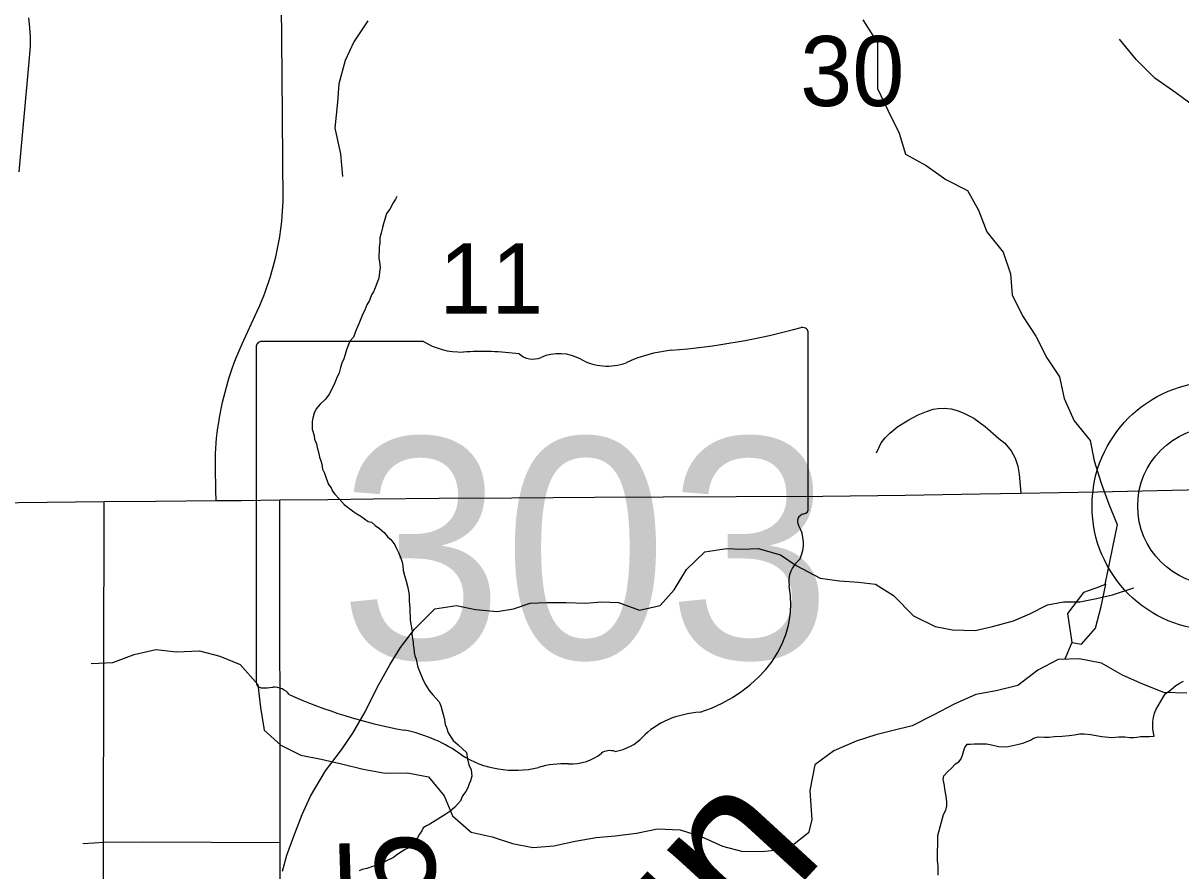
# Model space of a CAD drawing. Extents: x -21.1 to 50.3, y 0 to 22.1.
# Drawn here: x 2.692 to 3.383, y 20.064 to 20.57 of the extents above; entities that cross this region are included whole.
import ezdxf

# ---------------------------------------------------------------- set-up
doc = ezdxf.new("R2010")
doc.units = 0
for name, color, linetype in [('GM_X_Minor_Lake', 7, 'Continuous'), ('GM_X_Minor_River', 7, 'Continuous'), ('GM_X_Minor_River_Text', 7, 'Continuous'), ('GM_X_Section_Text', 7, 'Continuous'), ('GM_X_State_Location', 7, 'Continuous'), ('GM_X_State_Route', 7, 'Continuous'), ('GM_X_State_Shield', 7, 'Continuous'), ('GM_X_Township_Road', 7, 'Continuous'), ('GM_X_Township_Road_Text', 7, 'Continuous'), ('GM_X_Unincorporated', 7, 'Continuous')]:
    doc.layers.add(name, color=color, linetype=linetype)

msp = doc.modelspace()

# ---------------------------------------------------------------- linework, layer by layer
at = {"layer": 'GM_X_Minor_Lake'}
for points in [[(3.3386, 20.2351), (3.33479, 20.23356), (3.32528, 20.23012), (3.31579, 20.21756), (3.3184, 20.20027)], [(3.3386, 20.2351), (3.33479, 20.23356), (3.32528, 20.23012), (3.31579, 20.21756), (3.3184, 20.20027)], [(3.31837, 20.20027), (3.32419, 20.19932), (3.33254, 20.20883), (3.33595, 20.22177), (3.33859, 20.23508)], [(3.3184, 20.20027), (3.32419, 20.19932), (3.33254, 20.20883), (3.33595, 20.22177), (3.3386, 20.2351)]]:
    msp.add_lwpolyline(points, dxfattribs=at)
at = {"layer": 'GM_X_Minor_River'}
for points in [[(2.8981, 20.57159), (2.88975, 20.55907), (2.88444, 20.54808), (2.88064, 20.53404), (2.87988, 20.52304), (2.87835, 20.50749), (2.88175, 20.49232), (2.88288, 20.47867)], [(3.19351, 20.57225), (3.20228, 20.55857), (3.20232, 20.53118), (3.20843, 20.51826), (3.2153, 20.50458), (3.21912, 20.49203), (3.23131, 20.4852), (3.24311, 20.47685), (3.25606, 20.4704), (3.26255, 20.45862), (3.26751, 20.44569), (3.27742, 20.43353), (3.28163, 20.42061), (3.28279, 20.40806), (3.28889, 20.39552), (3.2969, 20.38335), (3.30339, 20.37043), (3.31102, 20.35903), (3.3137, 20.3461), (3.31981, 20.3328), (3.32934, 20.32102), (3.33164, 20.30886), (3.33584, 20.29555), (3.34043, 20.283), (3.34539, 20.27084), (3.33812, 20.23491)], [(3.39183, 20.52039), (3.3804, 20.52874), (3.36783, 20.53747), (3.35678, 20.54849), (3.34687, 20.56065)], [(2.91541, 20.46672), (2.91463, 20.46521), (2.91308, 20.46295), (2.91112, 20.45918), (2.90919, 20.45654), (2.90839, 20.45389), (2.90759, 20.45124), (2.90679, 20.4482), (2.90598, 20.44479), (2.90519, 20.44214), (2.90514, 20.4391), (2.90473, 20.43644), (2.9047, 20.43416), (2.90466, 20.43188), (2.90463, 20.4296), (2.90499, 20.42769), (2.90532, 20.42426), (2.90491, 20.42161), (2.90487, 20.41932), (2.90447, 20.41743), (2.90328, 20.4144), (2.90249, 20.41213), (2.90132, 20.40986), (2.90015, 20.40798), (2.89896, 20.40457), (2.89741, 20.40193), (2.89622, 20.3989), (2.89505, 20.39664), (2.89387, 20.39361), (2.89269, 20.39058), (2.89112, 20.38718), (2.88954, 20.38264), (2.88722, 20.38039), (2.88525, 20.37509), (2.88445, 20.37244), (2.88365, 20.36979), (2.88248, 20.36714), (2.88168, 20.36449), (2.88088, 20.36146), (2.87931, 20.35806), (2.87813, 20.35503), (2.87656, 20.35163), (2.87499, 20.34861), (2.87267, 20.3456), (2.86959, 20.3426), (2.86727, 20.33997), (2.86609, 20.33732), (2.86529, 20.33429), (2.86488, 20.33239), (2.86485, 20.32973), (2.86482, 20.32783), (2.86591, 20.32401), (2.86626, 20.32172), (2.86736, 20.31904), (2.86771, 20.31676), (2.86845, 20.31485), (2.8688, 20.31294), (2.86916, 20.31103), (2.86988, 20.30874), (2.87062, 20.30683), (2.87096, 20.30378), (2.87207, 20.30148), (2.87316, 20.29843), (2.87463, 20.2946), (2.87613, 20.29268), (2.87686, 20.29077), (2.87836, 20.28884), (2.88099, 20.28615), (2.88398, 20.28268), (2.88963, 20.27842), (2.89151, 20.27725), (2.89377, 20.2757), (2.89603, 20.27415), (2.8983, 20.2726), (2.90019, 20.27219), (2.90245, 20.27026), (2.90508, 20.26832), (2.90771, 20.266), (2.90996, 20.26331), (2.91184, 20.26176), (2.91408, 20.25869), (2.91519, 20.25639), (2.9163, 20.25409), (2.91777, 20.25065), (2.9185, 20.24835), (2.91885, 20.24607), (2.9192, 20.2434), (2.91991, 20.24035), (2.92101, 20.23691), (2.92173, 20.23386), (2.92208, 20.23195), (2.92244, 20.23004), (2.92279, 20.22814), (2.92275, 20.22509), (2.92307, 20.2209), (2.92303, 20.21824), (2.92338, 20.21596), (2.92335, 20.21368), (2.9237, 20.21139), (2.92405, 20.2091), (2.92441, 20.20719)], [(2.84704, 20.06375), (2.84969, 20.07323), (2.85387, 20.08461), (2.8588, 20.09751), (2.86374, 20.10851), (2.87284, 20.12368), (2.88233, 20.1362), (2.88915, 20.14606), (2.89636, 20.15895), (2.90357, 20.17337), (2.91116, 20.18702), (2.91761, 20.19726), (2.92595, 20.20826), (2.93809, 20.2204), (2.95098, 20.2223), (2.96235, 20.22002), (2.97524, 20.21889), (2.9851, 20.2204), (2.99495, 20.22382), (3.00481, 20.2242), (3.01618, 20.2242), (3.02793, 20.22383), (3.03779, 20.22458), (3.04764, 20.22421), (3.06015, 20.21966), (3.07266, 20.22231), (3.081, 20.2318), (3.08821, 20.24394), (3.09921, 20.25455), (3.1121, 20.25645), (3.12158, 20.25607), (3.13105, 20.25645), (3.14432, 20.25266), (3.15379, 20.24622), (3.16819, 20.23863), (3.17956, 20.23712), (3.19094, 20.23636), (3.20117, 20.23522), (3.21178, 20.2284), (3.2239, 20.21626), (3.23679, 20.20982), (3.24702, 20.20792), (3.26067, 20.20755), (3.2709, 20.20983), (3.28342, 20.21324), (3.29327, 20.21741), (3.30389, 20.22272), (3.31337, 20.22462), (3.32322, 20.22462), (3.33308, 20.22652), (3.34256, 20.22879), (3.35545, 20.23297)], [(2.92441, 20.20719), (2.92437, 20.20491), (2.92472, 20.20263), (2.92508, 20.20072), (2.92505, 20.19882), (2.92541, 20.19691), (2.92575, 20.19424), (2.9261, 20.19234), (2.92684, 20.19043), (2.92756, 20.18737), (2.92791, 20.18547), (2.92975, 20.18126), (2.93122, 20.17743), (2.93271, 20.17475), (2.93457, 20.17168), (2.93681, 20.16899), (2.93869, 20.16706), (2.94056, 20.16475), (2.94167, 20.16245), (2.94239, 20.1594), (2.94311, 20.15673), (2.94384, 20.15406), (2.94418, 20.15139), (2.94491, 20.14948), (2.94601, 20.14642), (2.94899, 20.14181), (2.952, 20.13911), (2.95463, 20.13679), (2.95688, 20.13448), (2.95759, 20.13067), (2.9583, 20.12723), (2.95978, 20.12417), (2.96011, 20.12036), (2.95931, 20.11771), (2.95852, 20.11582), (2.95773, 20.11355), (2.95656, 20.11128), (2.95462, 20.10865), (2.95344, 20.10562), (2.95151, 20.10374), (2.94997, 20.10186), (2.94689, 20.09924), (2.94458, 20.09775), (2.93499, 20.0918), (2.93308, 20.09069), (2.93116, 20.08957), (2.93037, 20.08768), (2.92883, 20.0858), (2.92765, 20.08353), (2.92533, 20.08052), (2.92301, 20.07789), (2.92071, 20.07678), (2.9188, 20.07567), (2.91534, 20.07343), (2.91342, 20.07194), (2.90883, 20.06972), (2.90499, 20.06749), (2.90079, 20.06641), (2.89735, 20.06531), (2.89468, 20.06459), (2.89277, 20.06385)], [(3.31842, 20.20028), (3.31424, 20.19035)], [(2.73293, 20.18779), (2.74578, 20.1884), (2.75856, 20.19317), (2.77137, 20.19606), (2.78388, 20.19476), (2.79749, 20.19537), (2.80964, 20.19217), (2.82184, 20.18707), (2.83226, 20.17511), (2.83402, 20.16148), (2.83615, 20.14785), (2.84614, 20.13892), (2.85797, 20.13306), (2.87012, 20.13061), (2.88227, 20.12779), (2.89519, 20.1246), (2.90847, 20.12218), (2.92171, 20.12241), (2.93423, 20.11997), (2.94351, 20.10875), (2.94864, 20.09669), (2.95978, 20.08702), (2.97231, 20.08421), (2.98448, 20.08024), (2.99663, 20.0778), (3.0091, 20.07878), (3.02191, 20.08166), (3.03435, 20.08377), (3.04569, 20.08473), (3.05852, 20.08647), (3.07096, 20.08897), (3.08459, 20.08845), (3.09714, 20.08449), (3.10972, 20.07864), (3.12189, 20.07544), (3.13512, 20.07567), (3.14871, 20.07704), (3.16103, 20.08675)], [(3.38701, 20.17011), (3.37331, 20.17047), (3.36075, 20.1754), (3.34857, 20.18071), (3.336, 20.18792), (3.32268, 20.19057), (3.31012, 20.19017), (3.29796, 20.18369), (3.28617, 20.17455), (3.27324, 20.17149), (3.26107, 20.16919), (3.24814, 20.16347), (3.23597, 20.15699), (3.22305, 20.15051), (3.21087, 20.14745), (3.20136, 20.14516), (3.18957, 20.14134), (3.17626, 20.13562), (3.16486, 20.12724), (3.16194, 20.11191), (3.16318, 20.09436), (3.16114, 20.08656)], [(3.3672, 20.15545), (3.36761, 20.15811), (3.3684, 20.16), (3.37268, 20.16717), (3.37424, 20.16981), (3.37655, 20.1713), (3.38039, 20.17467), (3.38308, 20.17615), (3.38499, 20.17727)], [(3.23849, 20.06137), (3.23852, 20.06404), (3.23856, 20.0667), (3.23823, 20.07013), (3.23843, 20.08496), (3.24164, 20.09747), (3.2432, 20.10011), (3.24362, 20.10276), (3.24365, 20.10504), (3.24332, 20.10847), (3.24261, 20.11267), (3.24227, 20.11495), (3.24155, 20.11839), (3.24196, 20.12066), (3.24428, 20.12329), (3.24659, 20.12516), (3.24891, 20.12779), (3.25082, 20.12891), (3.25237, 20.13079), (3.25316, 20.13306), (3.25396, 20.13571), (3.25437, 20.13761), (3.25591, 20.13949), (3.25782, 20.13946), (3.2601, 20.13981), (3.26276, 20.13977), (3.26505, 20.13974), (3.26733, 20.13971), (3.2696, 20.1393), (3.27453, 20.13809), (3.27948, 20.13802), (3.28482, 20.13909), (3.28901, 20.14017), (3.2936, 20.14201), (3.29552, 20.14313), (3.29819, 20.14385), (3.302, 20.1438), (3.30466, 20.14376), (3.30809, 20.14409), (3.31266, 20.14441), (3.31684, 20.14474), (3.31989, 20.14507), (3.32294, 20.14579), (3.32561, 20.14576), (3.32941, 20.14532), (3.33623, 20.14409), (3.34231, 20.14362), (3.3465, 20.14394), (3.34992, 20.1439), (3.35296, 20.14348), (3.35524, 20.14344), (3.35715, 20.1438), (3.35944, 20.14415), (3.36248, 20.14411), (3.36476, 20.14408), (3.36743, 20.14442), (3.36673, 20.14861), (3.36675, 20.15051), (3.36679, 20.15318), (3.3672, 20.15545)]]:
    msp.add_lwpolyline(points, dxfattribs=at)
at = {"layer": 'GM_X_State_Route'}
for points in [[(2.84553, 20.28548), (2.87423, 20.28579), (2.9014, 20.28614), (2.94057, 20.28643), (2.98403, 20.28675)], [(2.98403, 20.28675), (3.03343, 20.28706), (3.0743, 20.28731), (3.11789, 20.28743), (3.16976, 20.2878), (3.21883, 20.28836), (3.26368, 20.28902), (3.28793, 20.28953), (3.33361, 20.29027), (3.39622, 20.29163), (3.41981, 20.29237)], [(2.40939, 20.28139), (2.43498, 20.28152), (2.47747, 20.28205), (2.48841, 20.28218), (2.54659, 20.28269), (2.61253, 20.28328), (2.65498, 20.28367), (2.66882, 20.28379), (2.68951, 20.28398), (2.74059, 20.28444), (2.77141, 20.28472), (2.80741, 20.28506), (2.8227, 20.2852), (2.84553, 20.28548)]]:
    msp.add_lwpolyline(points, dxfattribs=at)
at = {"layer": 'GM_X_State_Shield'}
for p, q in [((3.161, 20.28045), (3.161, 20.38513)), ((2.83141, 20.37673), (2.83141, 20.17661)), ((2.93118, 20.38017), (2.83466, 20.38017)), ((3.16096, 20.28047), (3.161, 20.28045))]:
    msp.add_line(p, q, dxfattribs=at)
for centre, major_axis, start_param, end_param in [((3.04359, 20.653), (0.34952, 0), 4.814394, 5.042369), ((3.15734, 20.38557), (0.00367, 0), 6.141152, 7.989035), ((2.83519, 20.37716), (0.00382, 0), 1.712693, 3.28349), ((2.95416, 20.4034), (0.03703, 0), 4.042523, 4.731795), ((2.96644, 20.26782), (0.13295, 0), 1.404758, 1.657858), ((2.99663, 20.37819), (0.01068, 0), 3.836095, 5.185415), ((3.01231, 20.35506), (0.02221, 0), 0.950623, 2.079405), ((3.04098, 20.38679), (0.02672, 0), 4.081561, 5.145723), ((3.08818, 20.31905), (0.07032, 0), 1.699011, 2.107814), ((3.15708, 20.28004), (0.00393, 0), 5.05454, 6.418171), ((3.16015, 20.27276), (0.00568, 0), 1.883978, 3.671073), ((3.12402, 20.25953), (0.03409, 0), 5.934695, 6.695948), ((3.17414, 20.23664), (0.0248, 0), 2.387724, 3.262537), ((3.06317, 20.22332), (0.08742, 0), 5.101752, 6.440018), ((2.83522, 20.17617), (0.00385, 0), 3.00124, 4.508301), ((2.83581, 20.19664), (0.0294, 0), 4.665946, 4.897461), ((2.84182, 20.16506), (0.0106, 0), 0.519207, 1.627899), ((2.97565, 20.34486), (0.2524, 0), 4.195997, 4.488961), ((3.10003, 20.12043), (0.04788, 0), 1.647645, 2.488434), ((2.9004, 20.0867), (0.07897, 0), 0.823519, 1.323587), ((3.03937, 20.15721), (0.02824, 0), 4.937069, 5.64225), ((3.04258, 20.1297), (0.00752, 0), 1.147584, 2.315152), ((2.98581, 20.16407), (0.05011, 0), 4.026481, 4.996735), ((3.01476, 20.09488), (0.04118, 0), 1.495662, 1.94098), ((3.01842, 20.14908), (0.0267, 0), 4.691044, 5.507374)]:
    msp.add_ellipse(centre, major_axis=major_axis, ratio=0.8, start_param=start_param, end_param=end_param, dxfattribs=at)
at = {"layer": 'GM_X_Township_Road'}
for points in [[(2.80741, 20.28506), (2.8073, 20.29088), (2.80704, 20.30543), (2.80711, 20.31316), (2.80726, 20.31626), (2.80746, 20.31937), (2.80774, 20.32246), (2.80809, 20.32554), (2.80851, 20.32862), (2.80898, 20.33168), (2.80949, 20.33474), (2.81005, 20.33778), (2.81066, 20.34081), (2.81131, 20.34383), (2.81202, 20.34684), (2.81277, 20.34982), (2.81356, 20.35279), (2.81441, 20.35575), (2.8153, 20.35869), (2.81625, 20.36162), (2.81726, 20.36452), (2.81831, 20.36741), (2.81942, 20.37027), (2.82058, 20.37311), (2.82179, 20.37593), (2.82305, 20.37872), (2.83204, 20.39815), (2.8336, 20.40169), (2.83477, 20.40452), (2.8359, 20.40736), (2.83697, 20.41023), (2.838, 20.41311), (2.83897, 20.41601), (2.83989, 20.41893), (2.84077, 20.42186), (2.84159, 20.42481), (2.84236, 20.42776), (2.84307, 20.43074), (2.84374, 20.43373), (2.84435, 20.43672), (2.84491, 20.43973), (2.84542, 20.44274), (2.84588, 20.44577), (2.84629, 20.4488), (2.84663, 20.45184), (2.84693, 20.45489), (2.84717, 20.45794), (2.84737, 20.46099), (2.8475, 20.46404), (2.84689, 20.53904), (2.84568, 20.66549)], [(2.68988, 20.48154), (2.69287, 20.51439), (2.69565, 20.54492), (2.69659, 20.55659), (2.69671, 20.56189), (2.69624, 20.56778), (2.69554, 20.57356)], [(3.20175, 20.31369), (3.20322, 20.31694), (3.20458, 20.31953), (3.2068, 20.3225), (3.20964, 20.32534), (3.21445, 20.32929), (3.22111, 20.3334), (3.22666, 20.33629), (3.23148, 20.33832), (3.23556, 20.33962), (3.23852, 20.34008), (3.24222, 20.34026), (3.2463, 20.3398), (3.24982, 20.33897), (3.25348, 20.33757), (3.25989, 20.33423), (3.26657, 20.32941), (3.27486, 20.32226), (3.27829, 20.31929), (3.28205, 20.31489), (3.28455, 20.31035), (3.28607, 20.30571), (3.28694, 20.30089), (3.28793, 20.28953)], [(2.73967, 19.85475), (2.74016, 20.08103), (2.74059, 20.28444)], [(2.84452, 19.82521), (2.84502, 19.86796), (2.8449, 19.90856), (2.84502, 19.99446), (2.84553, 20.03403), (2.84566, 20.08086), (2.84553, 20.28548)], [(2.7279, 20.08031), (2.73438, 20.08069), (2.74016, 20.08103), (2.76358, 20.08114), (2.84566, 20.08086)]]:
    msp.add_lwpolyline(points, dxfattribs=at)
at = {"layer": 'GM_X_Unincorporated'}
for radius in [0.0744, 0.04716]:
    msp.add_circle((3.40482, 20.28185), radius, dxfattribs=at)

# ---------------------------------------------------------------- texts
at = {"layer": 'GM_X_Minor_River_Text'}
msp.add_text('Run', height=0.094728, rotation=47.42794, dxfattribs=at).set_placement((3.01491, 19.90159))
at = {"layer": 'GM_X_Section_Text'}
for s, p in [('30', (3.15614, 20.52078)), ('11', (2.94054, 20.39682))]:
    msp.add_text(s, height=0.041856, rotation=0.00001, dxfattribs=at).set_placement(p)
at = {"layer": 'GM_X_State_Location'}
for s, p in [('s', (2.9925, 20.26336)), ('r', (2.99249, 20.26336))]:
    msp.add_text(s, height=0.000189, dxfattribs=at).set_placement(p)
msp.add_text('303', height=0.000189, rotation=0.00001, dxfattribs=at).set_placement((2.92564, 20.24959))
at = {"layer": 'GM_X_State_Shield'}
msp.add_text('303', height=0.131836, dxfattribs=at).set_placement((2.88088, 20.19072))
at = {"layer": 'GM_X_Township_Road_Text'}
msp.add_text('T-175', height=0.056818, rotation=91.68485, dxfattribs=at).set_placement((2.94338, 19.8897))

doc.saveas('drawing.dxf')
